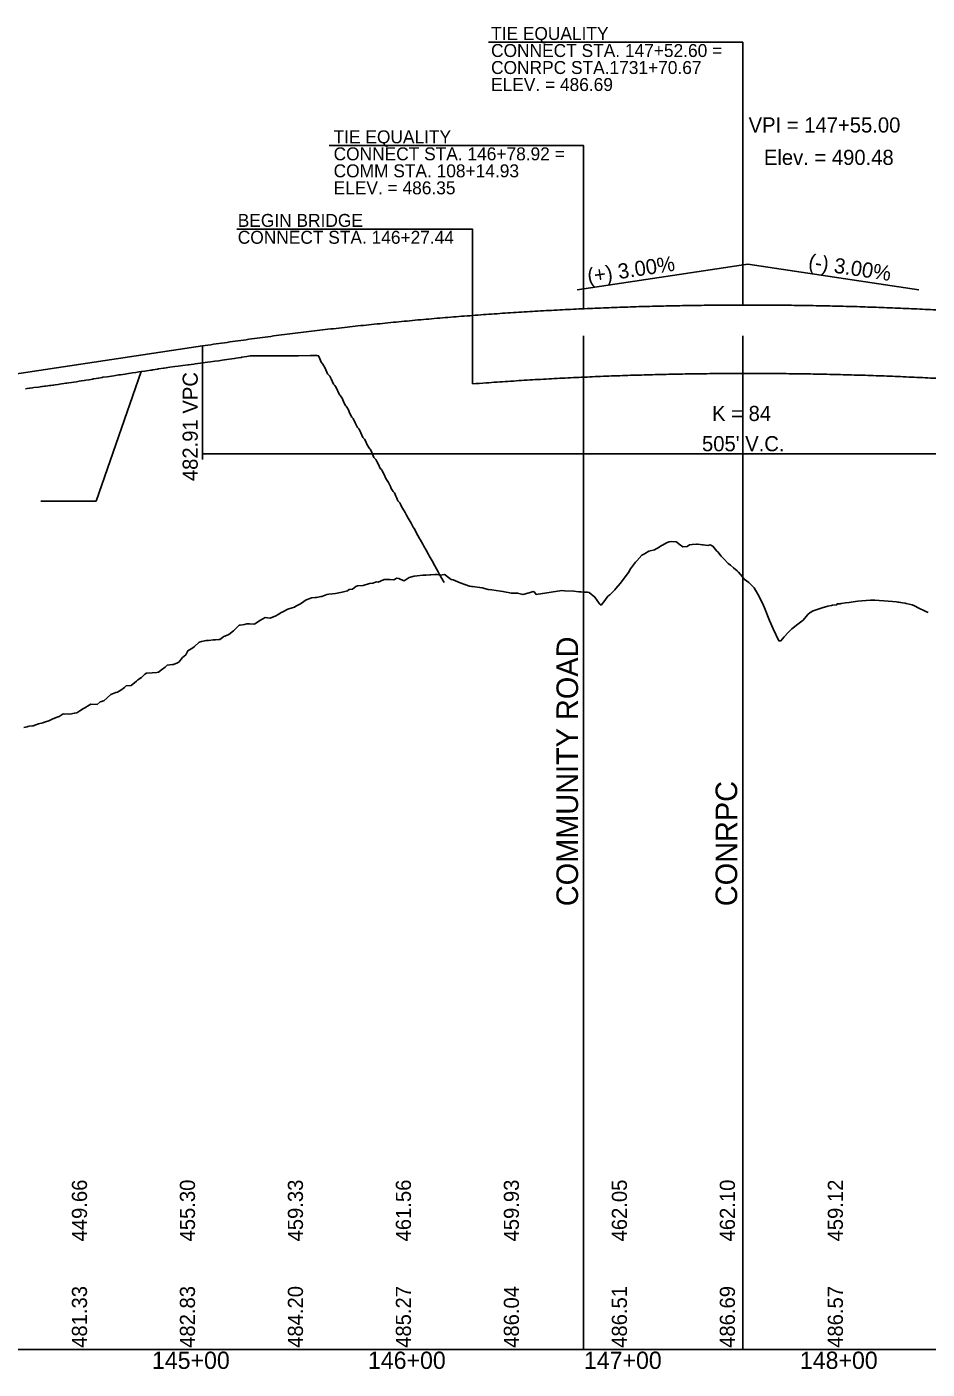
# Model space of a CAD drawing. Extents: x 2017200 to 2047700, y 854850 to 893350.
# Drawn here: x 2023921 to 2024338, y 865091 to 865712 of the extents above; entities that cross this region are included whole.
import ezdxf

# ---------------------------------------------------------------- set-up
doc = ezdxf.new("R2010")
doc.units = 0
for name, color, linetype in [('RD_DDB_GradeTX', 7, 'Continuous'), ('RD_DDB_Profile_Elev', 7, 'Continuous'), ('RD_DDB_Profile_EX', 7, 'Continuous'), ('RD_DDB_Profile_Lbl', 7, 'Continuous'), ('RD_DDB_Profile_PR', 7, 'Continuous'), ('RD_DDB_StaTX', 7, 'Continuous'), ('RD_DDB_StripGrade', 7, 'Continuous'), ('RD_DDB_VCLbl', 7, 'Continuous'), ('RD_GPK_Profile_Cell', 7, 'Continuous'), ('RD_PD_Bridge', 7, 'Continuous'), ('RD_PD_NON-PLOTTING', 7, 'Continuous')]:
    doc.layers.add(name, color=color, linetype=linetype)

msp = doc.modelspace()

# ---------------------------------------------------------------- linework, layer by layer
at = {"layer": 'RD_DDB_GradeTX'}
for p in [(2024175.89, 865590.53), (2024334.11, 865590.53)]:
    msp.add_line(p, (2024255, 865602.4), dxfattribs=at)
at = {"layer": 'RD_DDB_Profile_Elev'}
for points in [[(2023920.46, 865544.67), (2023921.31, 865544.8), (2023922.37, 865544.95), (2023922.67, 865545), (2023923.69, 865545.13), (2023924.42, 865545.23), (2023926.47, 865545.5), (2023928.03, 865545.7), (2023928.45, 865545.76), (2023929.25, 865545.86), (2023929.74, 865545.93), (2023930.83, 865546.08), (2023931.62, 865546.18), (2023932.25, 865546.27), (2023933.22, 865546.4), (2023933.52, 865546.44), (2023934.21, 865546.53), (2023935.65, 865546.72), (2023936.3, 865546.81), (2023939.21, 865547.22), (2023939.72, 865547.31), (2023940.54, 865547.44), (2023941.87, 865547.62), (2023942.97, 865547.8), (2023944.09, 865547.96), (2023945.42, 865548.18), (2023946.3, 865548.3), (2023947.79, 865548.56), (2023948.4, 865548.64), (2023949.95, 865548.91), (2023951.47, 865549.17), (2023951.97, 865549.25), (2023953.21, 865549.46), (2023954.29, 865549.65), (2023956, 865549.94), (2023956.34, 865550), (2023958.39, 865550.3), (2023961.35, 865550.74), (2023963.76, 865551.1), (2023964.08, 865551.15), (2023964.45, 865551.2), (2023966.66, 865551.53), (2023967.3, 865551.63), (2023969.18, 865551.91), (2023970.13, 865552.05), (2023971.67, 865552.28), (2023972.93, 865552.47), (2023974.13, 865552.65), (2023975.72, 865552.89), (2023976.57, 865553.02), (2023978.48, 865553.31), (2023979.01, 865553.39), (2023979.5, 865553.46), (2023981.63, 865553.79), (2023982.12, 865553.86), (2023984.42, 865554.21), (2023984.8, 865554.27), (2023987.29, 865554.65), (2023989.62, 865555), (2023991.28, 865555.21), (2023993.31, 865555.47), (2023995.62, 865555.76), (2023995.92, 865555.8), (2023998.42, 865556.12), (2023999.03, 865556.21), (2024001.5, 865556.52), (2024002.5, 865556.67), (2024004.78, 865556.96), (2024006.2, 865557.18), (2024008.16, 865557.43), (2024009.99, 865557.71), (2024011.55, 865557.92), (2024013.73, 865558.25), (2024014.86, 865558.4), (2024017.25, 865558.77), (2024017.96, 865558.87), (2024020.35, 865559.24), (2024020.73, 865559.29), (2024022.98, 865559.65), (2024024.56, 865559.9), (2024025.57, 865560), (2024042.32, 865560), (2024044.95, 865560), (2024046.91, 865560), (2024052.45, 865560.06), (2024053.18, 865560.05), (2024055.17, 865560.05), (2024055.5, 865560.03), (2024056.23, 865560), (2024056.77, 865558.52), (2024057.45, 865556.95), (2024058.2, 865556.16), (2024059.21, 865554.2), (2024060.36, 865551.6), (2024061.04, 865550.99), (2024061.46, 865550.52), (2024062.02, 865549.29), (2024063.07, 865546.78), (2024063.7, 865546.2), (2024064.09, 865545.74), (2024064.66, 865544.63), (2024065.44, 865542.78), (2024066.01, 865541.74), (2024066.35, 865541.42), (2024066.71, 865540.99), (2024067.28, 865540), (2024067.9, 865538.3), (2024068.68, 865536.96), (2024068.99, 865536.66), (2024069.32, 865536.26), (2024070.04, 865535), (2024070.57, 865533.57), (2024071.68, 865531.51), (2024072.23, 865531), (2024073.22, 865528.89), (2024074.2, 865526.81), (2024074.89, 865526.19), (2024075.19, 865525.67), (2024075.73, 865524.38), (2024076.72, 865522.12), (2024077.54, 865521.39), (2024077.97, 865520.61), (2024078.79, 865518.75), (2024079.73, 865517.08), (2024080.13, 865516.68), (2024080.54, 865515.96), (2024081.75, 865512.85), (2024082.75, 865511.94), (2024083.11, 865511.3), (2024083.92, 865509.65), (2024084.74, 865507.87), (2024085.3, 865507.32), (2024085.61, 865506.77), (2024086.56, 865505), (2024087.42, 865503.12), (2024088.67, 865501.29), (2024089.51, 865499.47), (2024089.89, 865498.57), (2024090.82, 865497.09), (2024091.33, 865496.48), (2024091.67, 865495.79), (2024092.07, 865494.99), (2024092.45, 865494.06), (2024092.97, 865492.78), (2024093.87, 865491.88), (2024094.17, 865491.28), (2024094.52, 865490.59), (2024095.11, 865489.4), (2024096.28, 865487.44), (2024097.01, 865486.12), (2024097.72, 865484.8), (2024099.08, 865482.49), (2024099.53, 865481.59), (2024100.08, 865480.6), (2024100.42, 865480), (2024101.57, 865477.98), (2024101.91, 865477.32), (2024102.44, 865476.37), (2024102.87, 865475.6), (2024103.2, 865475), (2024104.47, 865472.71), (2024104.93, 865471.89), (2024105.98, 865470), (2024107.08, 865468.01), (2024107.48, 865467.3), (2024108.75, 865465), (2024110, 865462.77), (2024111.53, 865460), (2024112.26, 865458.69), (2024114.3, 865455)], [(2023927.61, 865492.73), (2023953.21, 865492.73), (2023974.13, 865552.65)]]:
    msp.add_lwpolyline(points, dxfattribs=at)
at = {"layer": 'RD_DDB_Profile_EX'}
msp.add_lwpolyline([(2023919.75, 865387.9), (2023921.31, 865388.25), (2023921.67, 865388.33), (2023922.23, 865388.5), (2023923.69, 865388.64), (2023924.08, 865388.68), (2023925.36, 865389.09), (2023926.07, 865389.42), (2023926.49, 865389.62), (2023928.5, 865390.14), (2023928.9, 865390.24), (2023930.21, 865390.67), (2023930.83, 865390.87), (2023931.3, 865391.01), (2023931.64, 865391.17), (2023933.22, 865391.85), (2023933.7, 865392.06), (2023934.78, 865392.5), (2023935.6, 865392.81), (2023936.09, 865393), (2023937.98, 865394.19), (2023938.48, 865394.14), (2023940.36, 865394.19), (2023941.08, 865394.08), (2023943.25, 865394.48), (2023944.23, 865394.69), (2023945.63, 865395.64), (2023947.39, 865396.66), (2023948.01, 865397.05), (2023949.95, 865398.3), (2023950.82, 865398.66), (2023953.69, 865398.61), (2023955.16, 865399.84), (2023956.85, 865400.19), (2023960, 865403.2), (2023962.31, 865404.04), (2023963.15, 865404.23), (2023964.7, 865405.22), (2023966.31, 865406.47), (2023967.08, 865407.17), (2023969.47, 865407.35), (2023971.85, 865409.3), (2023972.61, 865409.94), (2023974.23, 865410.98), (2023975.77, 865412.59), (2023976.61, 865413.06), (2023979.22, 865413.2), (2023981.38, 865413.37), (2023982.07, 865413.54), (2023983.43, 865414.64), (2023985.23, 865415.83), (2023986.14, 865416.75), (2023988.53, 865417.03), (2023988.98, 865417.08), (2023990.91, 865417.8), (2023991.53, 865418.21), (2023993.29, 865420.33), (2023994.69, 865421.52), (2023995.68, 865423.42), (2023998.06, 865424.8), (2023998.74, 865425.38), (2024000.99, 865427.37), (2024002.07, 865427.64), (2024004.15, 865428.16), (2024005.21, 865428.15), (2024007.59, 865428.51), (2024008.5, 865428.56), (2024009.98, 865428.61), (2024010.45, 865428.65), (2024012.36, 865429.98), (2024013.61, 865430.56), (2024014.74, 865431.02), (2024016.76, 865432.6), (2024017.13, 865432.91), (2024018.26, 865434.1), (2024019.51, 865435.22), (2024019.91, 865435.33), (2024021.89, 865435.56), (2024023.07, 865435.89), (2024024.28, 865435.86), (2024026.22, 865435.74), (2024026.66, 865435.82), (2024028.01, 865436.74), (2024029.04, 865437.46), (2024029.37, 865437.61), (2024031.42, 865438.77), (2024032.53, 865438.62), (2024033.81, 865438.46), (2024035.68, 865439.24), (2024036.19, 865439.42), (2024037.77, 865440.31), (2024038.83, 865441.09), (2024039.34, 865441.24), (2024041.99, 865442.67), (2024044, 865443.34), (2024045.14, 865443.55), (2024045.72, 865444), (2024047.53, 865444.98), (2024048.29, 865445.4), (2024050.49, 865447), (2024051.45, 865447.34), (2024052.87, 865447.95), (2024054.6, 865448.15), (2024055.26, 865448.01), (2024057.29, 865448.47), (2024057.75, 865448.6), (2024060.02, 865449.41), (2024060.91, 865449.61), (2024062.64, 865449.81), (2024064.06, 865449.95), (2024064.79, 865450.05), (2024067.21, 865450.6), (2024069.56, 865451.22), (2024070.37, 865451.72), (2024071.94, 865451.95), (2024073.52, 865453.14), (2024074.32, 865453.44), (2024076.8, 865453.59), (2024079.83, 865454.58), (2024081.27, 865454.78), (2024082.98, 865455.31), (2024083.85, 865455.22), (2024086.24, 865456.29), (2024086.56, 865456.34), (2024088.62, 865456.35), (2024089.29, 865456.4), (2024091, 865456.28), (2024092.44, 865457.05), (2024093.39, 865456.94), (2024095.77, 865455.79), (2024096.32, 865456.12), (2024098.15, 865457.37), (2024098.75, 865457.47), (2024100.54, 865457.91), (2024101.9, 865458.06), (2024104.57, 865458.37), (2024105.3, 865458.44), (2024106.08, 865458.45), (2024107.69, 865458.54), (2024108.21, 865458.55), (2024110.07, 865458.78), (2024111.36, 865458.67), (2024112.45, 865458.49), (2024114.51, 865458.68), (2024114.84, 865458.53), (2024115.83, 865457.81), (2024117.67, 865456.43), (2024118.54, 865456.21), (2024121.75, 865454.93), (2024126.08, 865453.27), (2024127.07, 865453.21), (2024127.49, 865453.12), (2024131.97, 865452.54), (2024134.7, 865451.8), (2024136.39, 865451.56), (2024140.46, 865451.05), (2024141.56, 865450.87), (2024145.48, 865450.07), (2024146.52, 865450.04), (2024148.39, 865450.1), (2024150.86, 865449.42), (2024153.67, 865450.2), (2024155.51, 865450.83), (2024156.24, 865450.48), (2024156.95, 865449.5), (2024163.89, 865450.57), (2024168.81, 865451.32), (2024170.02, 865451.24), (2024174.43, 865450.95), (2024176.8, 865450.71), (2024177.58, 865450.65), (2024179.18, 865450.6), (2024180.73, 865450.58), (2024181.57, 865450.38), (2024184.14, 865448.27), (2024186.33, 865445.18), (2024187.04, 865444.55), (2024188.71, 865446.68), (2024190.19, 865448.68), (2024191.1, 865449.39), (2024193.35, 865451.63), (2024193.9, 865452.27), (2024195.86, 865454.51), (2024196.5, 865455.35), (2024198.25, 865457.72), (2024199.65, 865459.66), (2024200.63, 865461.28), (2024203.01, 865464.37), (2024203.65, 865465.12), (2024205.96, 865467.75), (2024207.06, 865468.36), (2024209.11, 865469.53), (2024211.72, 865470.16), (2024212.55, 865470.63), (2024213.41, 865471.11), (2024214.93, 865472.22), (2024215.42, 865472.29), (2024217.31, 865473.46), (2024218.57, 865473.82), (2024219.7, 865473.96), (2024221.73, 865473.91), (2024222.08, 865473.68), (2024223.17, 865472.79), (2024224.88, 865471.47), (2024226.85, 865471.71), (2024228.03, 865472.4), (2024229.23, 865472.57), (2024231.19, 865472.71), (2024231.61, 865472.74), (2024232.93, 865472.59), (2024234, 865472.41), (2024234.34, 865472.45), (2024236.38, 865472.14), (2024237.49, 865472.46), (2024238.76, 865471.79), (2024240.65, 865469.55), (2024241.14, 865469.2), (2024242.69, 865467.23), (2024243.8, 865465.96), (2024245.91, 865463.85), (2024246.95, 865463.11), (2024248.29, 865461.82), (2024250.11, 865460.42), (2024250.68, 865459.88), (2024252.44, 865457.62), (2024253.26, 865456.62), (2024255.44, 865455), (2024256.41, 865454.06), (2024257.83, 865452.56), (2024259.57, 865449.68), (2024260.21, 865448.5), (2024262.2, 865444.37), (2024262.72, 865443.35), (2024264.98, 865437.51), (2024266.66, 865433.53), (2024269.28, 865428.08), (2024270.28, 865428.08), (2024271.76, 865429.88), (2024273.66, 865431.92), (2024275.33, 865433.64), (2024276.55, 865434.54), (2024277.46, 865435.2), (2024279.96, 865437.1), (2024280.61, 865437.62), (2024282.83, 865440.19), (2024283.76, 865441.18), (2024285.22, 865441.98), (2024287.06, 865442.57), (2024289.4, 865443.31), (2024291.96, 865444.13), (2024293.79, 865444.44), (2024294.23, 865444.48), (2024296.07, 865444.65), (2024296.41, 865445.09), (2024297.79, 865445.17), (2024298.22, 865445.25), (2024300.2, 865445.62), (2024301.96, 865445.83), (2024303.79, 865446.08), (2024305.96, 865446.38), (2024307.79, 865446.54), (2024309.79, 865446.68), (2024311.79, 865446.8), (2024312.47, 865446.84), (2024313.04, 865446.82), (2024313.79, 865446.8), (2024315.79, 865446.7), (2024317.96, 865446.58), (2024319.96, 865446.45), (2024321.96, 865446.26), (2024323.79, 865446.05), (2024324.49, 865445.99), (2024324.84, 865445.93), (2024325.79, 865445.76), (2024326.52, 865445.67), (2024327.76, 865445.5), (2024328.24, 865445.36), (2024331.06, 865444.69), (2024332.17, 865444.15), (2024334.22, 865443.17), (2024336.83, 865441.88), (2024337.37, 865441.6), (2024338.51, 865441.15)], dxfattribs=at)
at = {"layer": 'RD_DDB_Profile_Lbl'}
for points in [[(2024252.6, 865583.46), (2024252.6, 865705.08), (2024134.84, 865705.08)], [(2024178.92, 865581.74), (2024178.92, 865657.28), (2024061.05, 865657.28)], [(2024127.44, 865578.63), (2024127.44, 865618.6), (2024018.32, 865618.6)]]:
    msp.add_lwpolyline(points, dxfattribs=at)
at = {"layer": 'RD_DDB_Profile_PR'}
msp.add_line((2023720, 865522.15), (2024002.5, 865564.53), dxfattribs=at)
msp.add_spline([(2024002.5, 865564.53), (2024012.6, 865566.01), (2024022.7, 865567.43), (2024032.8, 865568.8), (2024042.9, 865570.1), (2024053, 865571.34), (2024063.1, 865572.52), (2024073.2, 865573.65), (2024083.3, 865574.71), (2024093.4, 865575.71), (2024103.5, 865576.65), (2024113.6, 865577.52), (2024123.7, 865578.34), (2024133.8, 865579.1), (2024143.9, 865579.8), (2024154, 865580.43), (2024164.1, 865581.01), (2024174.2, 865581.52), (2024184.3, 865581.98), (2024194.4, 865582.37), (2024204.5, 865582.71), (2024214.6, 865582.98), (2024224.7, 865583.19), (2024234.8, 865583.34), (2024244.9, 865583.43), (2024255, 865583.46), (2024265.1, 865583.43), (2024275.2, 865583.34), (2024285.3, 865583.19), (2024295.4, 865582.98), (2024305.5, 865582.71), (2024315.6, 865582.37), (2024325.7, 865581.98), (2024335.8, 865581.52), (2024345.9, 865581.01), (2024356, 865580.43), (2024366.1, 865579.8), (2024376.2, 865579.1), (2024386.3, 865578.34), (2024396.4, 865577.52), (2024406.5, 865576.65), (2024416.6, 865575.71), (2024426.7, 865574.71), (2024436.8, 865573.65), (2024446.9, 865572.52), (2024457, 865571.34), (2024467.1, 865570.1), (2024477.2, 865568.8), (2024487.3, 865567.43), (2024497.4, 865566.01), (2024507.5, 865564.53)], degree=3, dxfattribs=at)
at = {"layer": 'RD_DDB_VCLbl'}
for p, q in [((2024002.5, 865512.03), (2024002.5, 865564.53)), ((2024002.5, 865514.53), (2024507.5, 865514.53))]:
    msp.add_line(p, q, dxfattribs=at)
at = {"layer": 'RD_GPK_Profile_Cell'}
msp.add_line((2020500, 865100), (2029700, 865100), dxfattribs=at)
at = {"layer": 'RD_PD_Bridge'}
msp.add_line((2024127.44, 865546.96), (2024127.44, 865578.63), dxfattribs=at)
msp.add_spline([(2024127.44, 865546.96), (2024133.8, 865547.43), (2024143.9, 865548.13), (2024154, 865548.77), (2024164.1, 865549.34), (2024174.2, 865549.86), (2024184.3, 865550.31), (2024194.4, 865550.71), (2024204.5, 865551.04), (2024214.6, 865551.31), (2024224.7, 865551.52), (2024234.8, 865551.67), (2024244.9, 865551.77), (2024255, 865551.8), (2024265.1, 865551.77), (2024275.2, 865551.67), (2024285.3, 865551.52), (2024295.4, 865551.31), (2024305.5, 865551.04), (2024315.6, 865550.71), (2024325.7, 865550.31), (2024335.8, 865549.86), (2024345.9, 865549.34), (2024356, 865548.77), (2024366.1, 865548.13), (2024376.2, 865547.43), (2024386.3, 865546.68), (2024396.4, 865545.86), (2024406.5, 865544.98), (2024416.6, 865544.04), (2024426.7, 865543.04), (2024436.8, 865541.98), (2024446.9, 865540.86), (2024457, 865539.68), (2024467.1, 865538.43), (2024477.2, 865537.13), (2024487.3, 865535.77), (2024487.44, 865535.75)], degree=3, dxfattribs=at)
at = {"layer": 'RD_PD_NON-PLOTTING'}
for p, q in [((2024178.92, 865100), (2024178.92, 865569.19)), ((2024252.6, 865100), (2024252.6, 865569.19))]:
    msp.add_line(p, q, dxfattribs=at)

# ---------------------------------------------------------------- texts
at = {"layer": 'RD_DDB_GradeTX'}
for s, rotation, p in [('(+) 3.00%', 8.53077, (2024181.2, 865593.35)), ('(-) 3.00%', 351.46923, (2024282.67, 865600.27))]:
    msp.add_text(s, height=7, rotation=rotation, dxfattribs=at).set_placement(p)
at = {"layer": 'RD_DDB_Profile_Lbl'}
for s, height, p in [('TIE EQUALITY', 6, (2024136.09, 865706.15)), ('CONNECT STA. 147+52.60 =', 6, (2024136.09, 865698.28)), ('CONRPC STA.1731+70.67', 6, (2024136.09, 865690.41)), ('ELEV. = 486.69', 6, (2024136.09, 865682.54)), ('TIE EQUALITY', 6, (2024063.19, 865658.32)), ('VPI = 147+55.00', 7, (2024255.34, 865663.32)), ('CONNECT STA. 146+78.92 =', 6, (2024063.19, 865650.45)), ('Elev. = 490.48', 7, (2024262.41, 865648.32)), ('COMM STA. 108+14.93', 6, (2024063.19, 865642.58)), ('ELEV. = 486.35', 6, (2024063.19, 865634.71)), ('BEGIN BRIDGE', 6, (2024018.81, 865619.63)), ('CONNECT STA. 146+27.44', 6, (2024018.81, 865611.82))]:
    msp.add_text(s, height=height, dxfattribs=at).set_placement(p)
at = {"layer": 'RD_DDB_StaTX'}
for s, p in [('145+00', (2023979.1, 865091)), ('145+00', (2023979.1, 865091)), ('146+00', (2024079.1, 865091)), ('146+00', (2024079.1, 865091)), ('147+00', (2024179.1, 865091)), ('147+00', (2024179.1, 865091)), ('148+00', (2024279.1, 865091)), ('148+00', (2024279.1, 865091))]:
    msp.add_text(s, height=8, dxfattribs=at).set_placement(p)
at = {"layer": 'RD_DDB_StripGrade'}
for s, p in [('482.91 VPC', (2024000.27, 865501.95)), ('449.66', (2023949, 865150)), ('455.30', (2023999, 865150)), ('459.33', (2024049, 865150)), ('461.56', (2024099, 865150)), ('459.93', (2024149, 865150)), ('462.05', (2024199, 865150)), ('462.10', (2024249, 865150)), ('459.12', (2024299, 865150)), ('481.33', (2023949, 865100.75)), ('482.83', (2023999, 865100.75)), ('484.20', (2024049, 865100.75)), ('485.27', (2024099, 865100.75)), ('486.04', (2024149, 865100.75)), ('486.51', (2024199, 865100.75)), ('486.69', (2024249, 865100.75)), ('486.57', (2024299, 865100.75))]:
    msp.add_text(s, height=7, rotation=90, dxfattribs=at).set_placement(p)
at = {"layer": 'RD_DDB_VCLbl'}
for s, p in [('K = 84', (2024238.41, 865529.78)), ("505' V.C.", (2024233.75, 865515.78))]:
    msp.add_text(s, height=7, dxfattribs=at).set_placement(p)
at = {"layer": 'RD_PD_NON-PLOTTING'}
for s, p in [('COMMUNITY ROAD', (2024176.37, 865305.19)), ('CONRPC', (2024250.05, 865305.19))]:
    msp.add_text(s, height=10, rotation=90, dxfattribs=at).set_placement(p)

doc.saveas('drawing.dxf')
